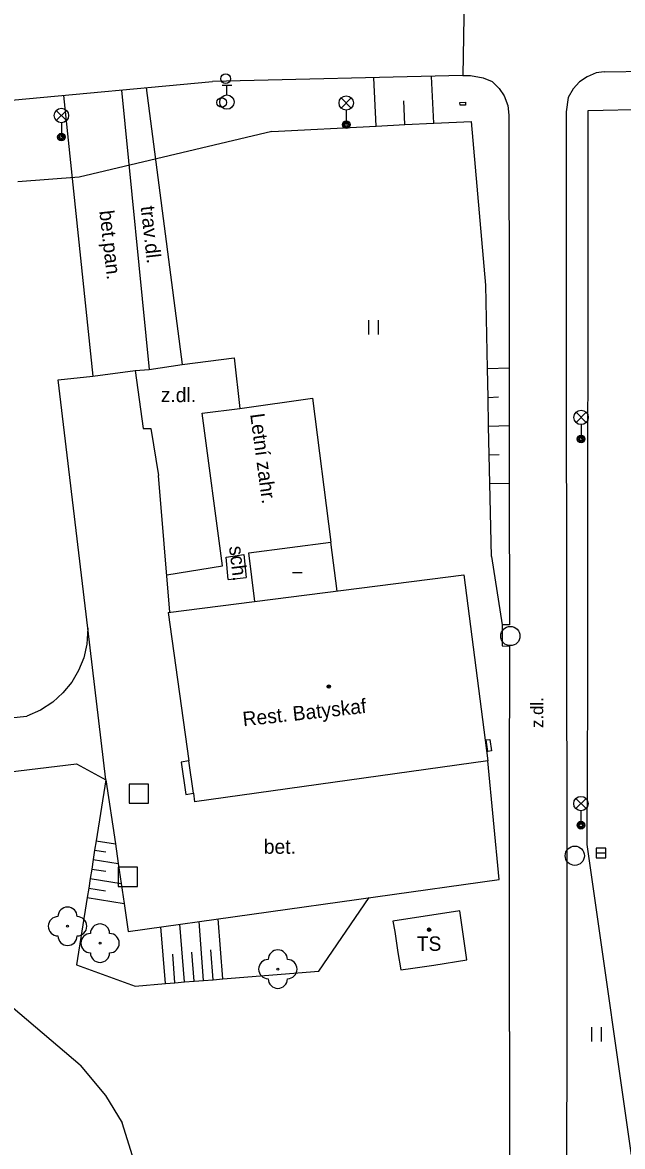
# Model space of a CAD drawing. Extents: x -641829 to -641525, y -1114855 to -1114359.
# Drawn here: x -641663.3 to -641632.1, y -1114729.4 to -1114670.9 of the extents above; entities that cross this region are included whole.
import ezdxf

# ---------------------------------------------------------------- set-up
doc = ezdxf.new("R2010")
doc.units = 0
for name, color, linetype in [('Vrstva 10', 7, 'Continuous'), ('Vrstva 11', 7, 'Continuous'), ('Vrstva 14', 7, 'Continuous'), ('Vrstva 15', 7, 'Continuous'), ('Vrstva 22', 7, 'Continuous'), ('Vrstva 24', 7, 'Continuous'), ('Vrstva 26', 7, 'Continuous'), ('Vrstva 27', 7, 'Continuous'), ('Vrstva 28', 7, 'Continuous'), ('Vrstva 33', 7, 'Continuous'), ('Vrstva 36', 7, 'Continuous'), ('Vrstva 39', 7, 'Continuous'), ('Vrstva 40', 7, 'Continuous'), ('Vrstva 41', 7, 'Continuous'), ('Vrstva 5', 7, 'Continuous'), ('Vrstva 7', 7, 'Continuous')]:
    doc.layers.add(name, color=color, linetype=linetype)

msp = doc.modelspace()

# ---------------------------------------------------------------- linework, layer by layer
at = {"layer": 'Vrstva 10'}
for p, q in [((-641658.13, -1114674.46), (-641656.68, -1114689)), ((-641658.93, -1114710.35), (-641659.87, -1114702.46)), ((-641660.27, -1114725.2), (-641671.07, -1114716.05)), ((-641660.27, -1114725.2), (-641658.96, -1114726.78)), ((-641658.96, -1114726.78), (-641658.08, -1114728.2)), ((-641657.27, -1114730.81), (-641658.08, -1114728.2))]:
    msp.add_line(p, q, dxfattribs=at)
for points in [[(-641659.62, -1114689.34), (-641657.41, -1114689.06), (-641656.68, -1114689), (-641654.96, -1114688.74)], [(-641657.41, -1114689.06), (-641656.99, -1114692.07), (-641656.59, -1114692.08), (-641656.2, -1114694.51)]]:
    msp.add_lwpolyline(points, dxfattribs=at)
at = {"layer": 'Vrstva 11'}
for p, q in [((-641640.28, -1114668.27), (-641640.36, -1114673.71)), ((-641633.01, -1114673.52), (-641624.34, -1114673.36)), ((-641640.36, -1114673.71), (-641653.39, -1114674.02)), ((-641640.36, -1114673.71), (-641639.97, -1114673.7)), ((-641639.97, -1114673.7), (-641639.31, -1114673.82)), ((-641639.31, -1114673.82), (-641638.83, -1114674.02)), ((-641633.89, -1114673.77), (-641634.3, -1114674.04)), ((-641633.42, -1114673.57), (-641633.89, -1114673.77)), ((-641633.01, -1114673.52), (-641633.42, -1114673.57)), ((-641663.84, -1114674.99), (-641653.39, -1114674.02)), ((-641656.84, -1114674.34), (-641654.96, -1114688.74)), ((-641638.83, -1114674.02), (-641638.48, -1114674.38)), ((-641638.48, -1114674.38), (-641638.22, -1114674.77)), ((-641634.63, -1114674.4), (-641634.88, -1114674.85)), ((-641634.3, -1114674.04), (-641634.63, -1114674.4)), ((-641661.14, -1114674.74), (-641659.62, -1114689.34)), ((-641638.22, -1114674.77), (-641638.03, -1114675.26)), ((-641634.88, -1114674.85), (-641634.99, -1114675.59)), ((-641638.03, -1114675.26), (-641637.97, -1114675.77)), ((-641634.99, -1114675.59), (-641634.98, -1114687.1)), ((-641637.97, -1114675.77), (-641637.96, -1114686.72)), ((-641634.98, -1114687.1), (-641634.97, -1114702.76)), ((-641655.6, -1114701.63), (-641656.2, -1114694.51)), ((-641652.57, -1114699.93), (-641651.63, -1114699.83)), ((-641637.94, -1114702.29), (-641638.32, -1114702.28)), ((-641638.32, -1114702.28), (-641638.32, -1114703.38)), ((-641634.97, -1114702.76), (-641634.96, -1114713.91)), ((-641638.32, -1114703.38), (-641637.94, -1114703.4)), ((-641637.94, -1114703.4), (-641637.96, -1114710.9)), ((-641671.03, -1114707.86), (-641663.04, -1114707.04)), ((-641639.15, -1114708.27), (-641638.95, -1114708.25)), ((-641639.07, -1114708.87), (-641639.15, -1114708.27)), ((-641638.95, -1114708.25), (-641638.88, -1114708.84)), ((-641638.88, -1114708.84), (-641639.07, -1114708.87)), ((-641638.47, -1114715.53), (-641639.06, -1114709.37)), ((-641637.96, -1114710.9), (-641637.95, -1114712.89)), ((-641637.95, -1114712.89), (-641637.95, -1114723.45)), ((-641634.96, -1114713.91), (-641634.96, -1114723.48)), ((-641657.77, -1114718.24), (-641638.47, -1114715.53)), ((-641637.95, -1114723.45), (-641637.93, -1114723.45)), ((-641637.93, -1114723.45), (-641637.93, -1114735.4)), ((-641634.96, -1114723.48), (-641634.97, -1114738.41))]:
    msp.add_line(p, q, dxfattribs=at)
for points in [[(-641637.96, -1114686.72), (-641637.96, -1114688.92), (-641637.95, -1114691.92), (-641637.95, -1114694.92), (-641637.94, -1114702.29)], [(-641654.96, -1114688.74), (-641652.26, -1114688.39), (-641651.97, -1114691.03)], [(-641659.87, -1114702.46), (-641661.41, -1114689.54), (-641659.62, -1114689.34)], [(-641652.57, -1114699.93), (-641652.67, -1114698.77), (-641651.76, -1114698.63), (-641651.63, -1114699.83)], [(-641659.87, -1114702.46), (-641659.93, -1114703.29), (-641660.09, -1114704), (-641660.36, -1114704.67), (-641660.71, -1114705.27), (-641661.18, -1114705.83), (-641661.69, -1114706.31), (-641662.33, -1114706.72), (-641663.04, -1114707.04)], [(-641669.54, -1114710.61), (-641660.46, -1114709.52), (-641658.93, -1114710.35)], [(-641658.93, -1114710.35), (-641658.44, -1114713.68), (-641658.29, -1114714.71), (-641658.14, -1114715.75), (-641657.98, -1114716.79), (-641657.77, -1114718.24)]]:
    msp.add_lwpolyline(points, dxfattribs=at)
at = {"layer": 'Vrstva 14'}
for p, q in [((-641639.17, -1114684.62), (-641639.92, -1114676.09)), ((-641650.3, -1114676.61), (-641660.32, -1114679)), ((-641660.32, -1114679), (-641663.51, -1114679.24)), ((-641638.88, -1114698.73), (-641638.32, -1114702.28))]:
    msp.add_line(p, q, dxfattribs=at)
for points in [[(-641650.3, -1114676.61), (-641644.88, -1114676.34), (-641643.38, -1114676.26), (-641641.88, -1114676.19), (-641639.92, -1114676.09)], [(-641638.88, -1114698.73), (-641638.96, -1114694.94), (-641638.99, -1114693.44), (-641639.02, -1114691.95), (-641639.05, -1114690.45), (-641639.08, -1114688.95), (-641639.17, -1114684.62)], [(-641658.93, -1114710.35), (-641659.44, -1114713.52), (-641659.52, -1114714.01), (-641659.6, -1114714.5), (-641659.67, -1114715), (-641659.75, -1114715.49), (-641659.83, -1114715.98), (-641659.91, -1114716.48), (-641660.47, -1114719.97), (-641657.41, -1114721.08), (-641655.84, -1114720.95), (-641655.34, -1114720.91), (-641654.84, -1114720.87), (-641654.35, -1114720.83), (-641653.85, -1114720.79), (-641653.35, -1114720.75), (-641652.85, -1114720.71), (-641647.86, -1114720.31), (-641645.24, -1114716.48)]]:
    msp.add_lwpolyline(points, dxfattribs=at)
at = {"layer": 'Vrstva 15'}
for p, q in [((-641644.88, -1114676.34), (-641645, -1114673.82)), ((-641641.88, -1114676.19), (-641642, -1114673.75)), ((-641643.38, -1114676.26), (-641643.44, -1114675.02)), ((-641639.08, -1114688.95), (-641637.96, -1114688.92)), ((-641639.05, -1114690.45), (-641638.5, -1114690.43)), ((-641639.02, -1114691.95), (-641637.95, -1114691.92)), ((-641638.99, -1114693.44), (-641638.47, -1114693.43)), ((-641638.96, -1114694.94), (-641637.95, -1114694.92)), ((-641659.44, -1114713.52), (-641658.44, -1114713.68)), ((-641659.52, -1114714.01), (-641658.94, -1114714.1)), ((-641659.6, -1114714.5), (-641658.29, -1114714.71)), ((-641659.67, -1114715), (-641658.94, -1114715.11)), ((-641659.83, -1114715.98), (-641658.95, -1114716.13)), ((-641659.75, -1114715.49), (-641658.14, -1114715.75)), ((-641659.91, -1114716.48), (-641657.98, -1114716.79)), ((-641653.85, -1114720.79), (-641654.09, -1114717.72)), ((-641652.85, -1114720.71), (-641653.1, -1114717.58)), ((-641655.84, -1114720.95), (-641656.08, -1114718)), ((-641654.84, -1114720.87), (-641655.09, -1114717.86)), ((-641655.34, -1114720.91), (-641655.46, -1114719.42)), ((-641654.35, -1114720.83), (-641654.47, -1114719.31)), ((-641653.35, -1114720.75), (-641653.47, -1114719.2))]:
    msp.add_line(p, q, dxfattribs=at)
at = {"layer": 'Vrstva 22'}
for centre in [(-641660.93, -1114717.97), (-641659.24, -1114718.85), (-641649.99, -1114720.2)]:
    msp.add_circle(centre, 0.05, dxfattribs=at)
for centre, start, end in [((-641660.93, -1114717.47), 0, 180), ((-641661.43, -1114717.97), 90, 270), ((-641660.43, -1114717.97), 270, 90), ((-641659.74, -1114718.85), 90, 270), ((-641659.24, -1114718.35), 0, 180), ((-641658.74, -1114718.85), 270, 90), ((-641660.93, -1114718.47), 180, 0), ((-641659.24, -1114719.35), 180, 0), ((-641649.99, -1114719.7), 0, 180), ((-641650.49, -1114720.2), 90, 270), ((-641649.49, -1114720.2), 270, 90), ((-641649.99, -1114720.7), 180, 0)]:
    msp.add_arc(centre, 0.5, start, end, dxfattribs=at)
at = {"layer": 'Vrstva 24'}
for points in [[(-641640.52, -1114675.11), (-641640.22, -1114675.1), (-641640.22, -1114675.25), (-641640.51, -1114675.25), (-641640.52, -1114675.11)], [(-641654.78, -1114711.11), (-641654.38, -1114711.05), (-641654.62, -1114709.37), (-641655.01, -1114709.43), (-641654.78, -1114711.11)]]:
    msp.add_lwpolyline(points, dxfattribs=at)
at = {"layer": 'Vrstva 26'}
for points in [[(-641656.72, -1114710.57), (-641657.72, -1114710.57), (-641657.72, -1114711.57), (-641656.72, -1114711.57)], [(-641657.29, -1114714.9), (-641658.29, -1114714.9), (-641658.29, -1114715.9), (-641657.29, -1114715.9)]]:
    msp.add_lwpolyline(points, close=True, dxfattribs=at)
at = {"layer": 'Vrstva 27'}
msp.add_line((-641632.93, -1114714.16), (-641633.43, -1114714.16), dxfattribs=at)
msp.add_lwpolyline([(-641632.93, -1114713.91), (-641633.43, -1114713.91), (-641633.43, -1114714.41), (-641632.93, -1114714.41)], close=True, dxfattribs=at)
for centre in [(-641637.89, -1114702.87), (-641634.54, -1114714.3)]:
    msp.add_circle(centre, 0.5, dxfattribs=at)
at = {"layer": 'Vrstva 28'}
for p, q in [((-641652.89, -1114674.214), (-641652.39, -1114674.214)), ((-641652.64, -1114674.714), (-641652.64, -1114674.214))]:
    msp.add_line(p, q, dxfattribs=at)
for centre, radius in [((-641652.7, -1114673.87), 0.25), ((-641652.91, -1114675.11), 0.25), ((-641652.64, -1114675.09), 0.375)]:
    msp.add_circle(centre, radius, dxfattribs=at)
at = {"layer": 'Vrstva 33'}
for p, q in [((-641646.694, -1114675.4), (-641646.166, -1114674.87)), ((-641646.694, -1114674.87), (-641646.166, -1114675.4)), ((-641661.514, -1114676.05), (-641660.986, -1114675.52)), ((-641661.514, -1114675.52), (-641660.986, -1114676.05)), ((-641646.43, -1114675.51), (-641646.43, -1114676.26)), ((-641661.25, -1114676.16), (-641661.25, -1114676.91)), ((-641634.475, -1114691.76), (-641633.945, -1114691.23)), ((-641634.475, -1114691.23), (-641633.945, -1114691.76)), ((-641634.21, -1114691.87), (-641634.21, -1114692.62)), ((-641634.485, -1114711.85), (-641633.955, -1114711.32)), ((-641634.485, -1114711.32), (-641633.955, -1114711.85)), ((-641634.22, -1114711.96), (-641634.22, -1114712.71))]:
    msp.add_line(p, q, dxfattribs=at)
for centre, radius in [((-641646.43, -1114675.135), 0.375), ((-641661.25, -1114675.785), 0.375), ((-641646.43, -1114676.26), 0.2), ((-641646.43, -1114676.26), 0.145), ((-641646.43, -1114676.26), 0.0876), ((-641661.25, -1114676.91), 0.2), ((-641661.25, -1114676.91), 0.145), ((-641661.25, -1114676.91), 0.0876), ((-641634.21, -1114691.495), 0.375), ((-641634.21, -1114692.62), 0.2), ((-641634.21, -1114692.62), 0.145), ((-641634.21, -1114692.62), 0.0876), ((-641634.22, -1114711.585), 0.375), ((-641634.22, -1114712.71), 0.2), ((-641634.22, -1114712.71), 0.145), ((-641634.22, -1114712.71), 0.0876)]:
    msp.add_circle(centre, radius, dxfattribs=at)
at = {"layer": 'Vrstva 36'}
for p, q in [((-641645.254, -1114687.183), (-641645.254, -1114686.433)), ((-641644.754, -1114687.183), (-641644.754, -1114686.433)), ((-641633.654, -1114723.973), (-641633.654, -1114723.223)), ((-641633.154, -1114723.973), (-641633.154, -1114723.223))]:
    msp.add_line(p, q, dxfattribs=at)
at = {"layer": 'Vrstva 39'}
msp.add_line((-641649.23, -1114699.56), (-641648.73, -1114699.56), dxfattribs=at)
for centre, radius in [((-641647.34, -1114705.5), 0.09), ((-641647.34, -1114705.5), 0.0398), ((-641642.12, -1114718.15), 0.09), ((-641642.12, -1114718.15), 0.0398)]:
    msp.add_circle(centre, radius, dxfattribs=at)
at = {"layer": 'Vrstva 5'}
for p, q in [((-641646.91, -1114700.53), (-641647.24, -1114697.99)), ((-641655.69, -1114701.65), (-641640.31, -1114699.69)), ((-641640.31, -1114699.69), (-641639.06, -1114709.37)), ((-641655.69, -1114701.65), (-641654.62, -1114709.37)), ((-641639.06, -1114709.37), (-641654.32, -1114711.5)), ((-641654.38, -1114711.05), (-641654.32, -1114711.5))]:
    msp.add_line(p, q, dxfattribs=at)
for points in [[(-641655.76, -1114699.69), (-641652.86, -1114699.21), (-641653.92, -1114691.28), (-641651.97, -1114691.03), (-641648.18, -1114690.5), (-641647.24, -1114697.99)], [(-641651.18, -1114701.07), (-641651.49, -1114698.54), (-641647.24, -1114697.99)], [(-641640.16, -1114719.72), (-641640.52, -1114717.17), (-641644.01, -1114717.7)], [(-641644.01, -1114717.7), (-641643.91, -1114718.24), (-641643.74, -1114719.34), (-641643.59, -1114720.24), (-641642.97, -1114720.15), (-641641.87, -1114719.99), (-641640.16, -1114719.72)]]:
    msp.add_lwpolyline(points, dxfattribs=at)
at = {"layer": 'Vrstva 7'}
for p, q in [((-641633.86, -1114705.8), (-641633.85, -1114675.52)), ((-641633.85, -1114675.52), (-641627.16, -1114675.37)), ((-641633.89, -1114713.72), (-641633.86, -1114705.8))]:
    msp.add_line(p, q, dxfattribs=at)
msp.add_lwpolyline([(-641631.05, -1114733.72), (-641631.35, -1114731.58), (-641633.89, -1114713.72)], dxfattribs=at)

# ---------------------------------------------------------------- texts
at = {"layer": 'Vrstva 40'}
msp.add_text('z.dl.', height=0.65, rotation=90.03659, dxfattribs=at).set_placement((-641636.18, -1114707.65))
at = {"layer": 'Vrstva 41'}
for s, height, rotation, p in [('bet.pan.', 0.75, 276.47951, (-641659.28, -1114680.76)), ('trav.dl.', 0.75, 276.47951, (-641657.13, -1114680.53)), ('Letní zahr.', 0.75, 277.61155, (-641651.43, -1114691.33)), ('sch.', 0.7499, 276.88173, (-641652.53, -1114698.22)), ('Rest. Batyskaf', 0.75, 6.26802, (-641651.78, -1114707.57))]:
    msp.add_text(s, height=height, rotation=rotation, dxfattribs=at).set_placement(p)
for s, p in [('z.dl.', (-641656.08, -1114690.7)), ('bet.', (-641650.72, -1114714.2)), ('TS', (-641642.76, -1114719.25))]:
    msp.add_text(s, height=0.75, dxfattribs=at).set_placement(p)

doc.saveas('drawing.dxf')
